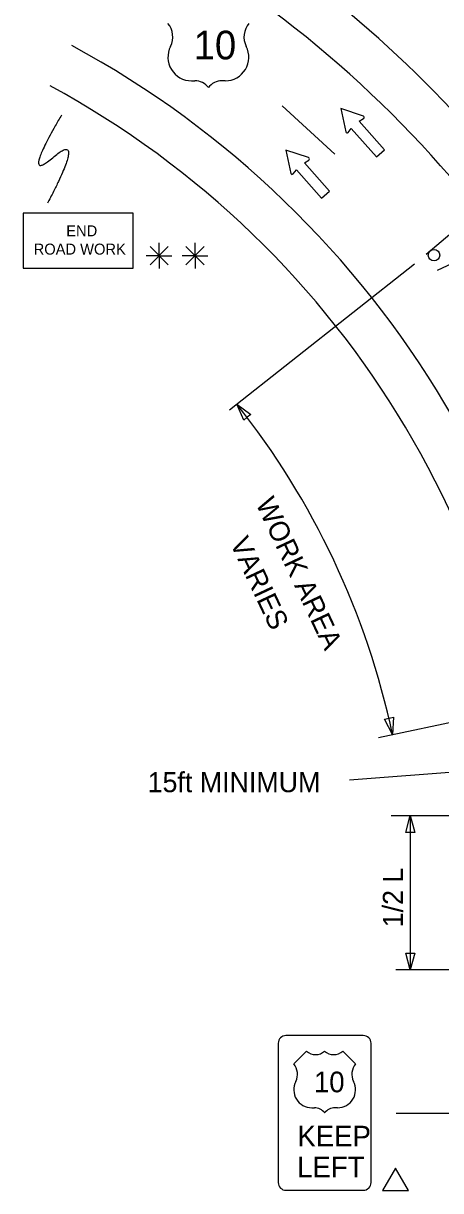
# Model space of a CAD drawing. Extents: x 16563 to 19504, y 6261 to 8279.
# Drawn here: x 16730.9 to 16876.6, y 7653.2 to 8060.6 of the extents above; entities that cross this region are included whole.
import ezdxf

# ---------------------------------------------------------------- set-up
doc = ezdxf.new("R2010")
doc.units = 0
for name, color, linetype in [('ALI_LEGAL_EX', 7, 'Continuous'), ('MT_SCRATCH_LEVEL_A', 7, 'Continuous'), ('MT_SCRATCH_LEVEL_E', 7, 'Continuous'), ('PAVT_EDGE_EX', 7, 'Continuous'), ('TRAFFIC_SIGNS_PR', 7, 'Continuous'), ('TYPICAL_EX', 7, 'Continuous'), ('TYPICAL_TEXT_DIMEN_PR', 7, 'Continuous')]:
    doc.layers.add(name, color=color, linetype=linetype)

msp = doc.modelspace()

# ---------------------------------------------------------------- linework, layer by layer
at = {"layer": 'ALI_LEGAL_EX'}
msp.add_lwpolyline([(16839.69, 8014.86), (16821.25, 8031.75)], dxfattribs=at)
msp.add_arc((16585.01, 7943.78), 364, 0, 40.1909, dxfattribs=at)
at = {"layer": 'MT_SCRATCH_LEVEL_A'}
for p, q in [((16889.81, 7995.4), (16871.52, 7979.86)), ((16875.47, 7974.42), (16897.61, 7984.74))]:
    msp.add_line(p, q, dxfattribs=at)
at = {"layer": 'MT_SCRATCH_LEVEL_E'}
for p, q in [((16841.74, 8030.81), (16843.46, 8022.67)), ((16849.64, 8028.15), (16841.74, 8030.81)), ((16841.74, 8030.81), (16843.46, 8022.67)), ((16849.64, 8028.15), (16841.74, 8030.81)), ((16848.2, 8026.37), (16849.74, 8027.31)), ((16848.2, 8026.37), (16849.74, 8027.31)), ((16856.99, 8016.45), (16848.2, 8026.37)), ((16856.99, 8016.45), (16848.2, 8026.37)), ((16844.28, 8022.47), (16845.4, 8023.89)), ((16844.28, 8022.47), (16845.4, 8023.89)), ((16845.4, 8023.89), (16854.19, 8013.97)), ((16845.4, 8023.89), (16854.19, 8013.97)), ((16822.58, 8016.35), (16824.31, 8008.2)), ((16830.49, 8013.68), (16822.58, 8016.35)), ((16822.58, 8016.35), (16824.31, 8008.2)), ((16830.49, 8013.68), (16822.58, 8016.35)), ((16854.19, 8013.97), (16856.99, 8016.45)), ((16854.19, 8013.97), (16856.99, 8016.45)), ((16825.12, 8008.01), (16826.25, 8009.43)), ((16825.12, 8008.01), (16826.25, 8009.43)), ((16826.25, 8009.43), (16835.04, 7999.51)), ((16826.25, 8009.43), (16835.04, 7999.51)), ((16829.05, 8011.91), (16830.58, 8012.85)), ((16829.05, 8011.91), (16830.58, 8012.85)), ((16837.84, 8001.99), (16829.05, 8011.91)), ((16837.84, 8001.99), (16829.05, 8011.91)), ((16835.04, 7999.51), (16837.84, 8001.99)), ((16835.04, 7999.51), (16837.84, 8001.99))]:
    msp.add_line(p, q, dxfattribs=at)
for centre, start, end in [((16849.48, 8027.7), 301.5941, 71.331), ((16849.48, 8027.7), 301.5941, 71.331), ((16843.92, 8022.77), 191.9827, 321.5217), ((16843.92, 8022.77), 191.9827, 321.5217), ((16830.33, 8013.24), 301.5941, 71.331), ((16830.33, 8013.24), 301.5941, 71.331), ((16824.76, 8008.3), 191.9827, 321.5217), ((16824.76, 8008.3), 191.9827, 321.5217)]:
    msp.add_arc(centre, 0.463, start, end, dxfattribs=at)
at = {"layer": 'PAVT_EDGE_EX'}
for radius, start in [(404, 21.0961), (388, 14.0482), (340, 0), (324, 0)]:
    msp.add_arc((16586.02, 7753.78), radius, start, 61.5719, dxfattribs=at)
at = {"layer": 'TRAFFIC_SIGNS_PR'}
for p, q in [((16819.92, 7704.61), (16819.92, 7656.01)), ((16849.62, 7707.31), (16822.62, 7707.31)), ((16852.32, 7656.01), (16852.32, 7704.61)), ((16822.62, 7653.31), (16849.62, 7653.31))]:
    msp.add_line(p, q, dxfattribs=at)
msp.add_lwpolyline([(16730.9, 7975.1), (16769.31, 7975.1), (16769.31, 7994.3), (16730.9, 7994.3)], close=True, dxfattribs=at)
msp.add_circle((16874.31, 7979.63), 2, dxfattribs=at)
for centre, start, end in [((16822.62, 7704.61), 90, 180), ((16849.62, 7704.61), 0, 90), ((16822.62, 7656.01), 180, 270), ((16849.62, 7656.01), 270, 0)]:
    msp.add_arc(centre, 2.7, start, end, dxfattribs=at)
at = {"layer": 'TYPICAL_EX'}
for p, q in [((16789.62, 8040.49), (16790.8, 8040.49)), ((16801.42, 8040.49), (16800.24, 8040.49)), ((16825.32, 7697.41), (16829.82, 7701.91)), ((16846.92, 7697.41), (16842.42, 7701.91)), ((16831.62, 7682.1), (16832.52, 7682.1)), ((16840.63, 7682.1), (16839.73, 7682.1))]:
    msp.add_line(p, q, dxfattribs=at)
for centre, radius, start, end in [((16775.78, 8055.83), 7.31, 333.0977, 40.1936), ((16815.26, 8055.83), 7.31, 139.8064, 206.9023), ((16789.63, 8048.74), 8.24, 152.6698, 269.9013), ((16801.41, 8048.74), 8.24, 270.0987, 27.3302), ((16790.81, 8034.59), 5.91, 37.1038, 90.1385), ((16800.23, 8034.59), 5.91, 89.8615, 142.8962), ((16832.97, 7705.19), 4.55, 226.1404, 313.8596), ((16839.27, 7705.19), 4.55, 226.1404, 313.8596), ((16821.06, 7693.81), 5.58, 333.0977, 40.1936), ((16851.19, 7693.81), 5.58, 139.8064, 206.9023), ((16831.63, 7688.4), 6.29, 152.6698, 269.9013), ((16840.62, 7688.4), 6.29, 270.0987, 27.3302), ((16832.53, 7677.59), 4.51, 37.1038, 90.1385), ((16839.72, 7677.59), 4.51, 89.8615, 142.8962)]:
    msp.add_arc(centre, radius, start, end, dxfattribs=at)
at = {"layer": 'TYPICAL_TEXT_DIMEN_PR'}
for p, q in [((16775.14, 7982.66), (16781.52, 7976.28)), ((16781.52, 7982.66), (16775.14, 7976.28)), ((16778.33, 7979.47), (16778.33, 7983.93)), ((16787.7, 7982.66), (16794.08, 7976.28)), ((16794.08, 7982.66), (16787.7, 7976.28)), ((16790.89, 7979.47), (16790.89, 7983.93)), ((16778.33, 7979.47), (16773.8, 7979.47)), ((16778.33, 7979.47), (16781.52, 7979.47)), ((16778.33, 7979.47), (16782.81, 7979.47)), ((16778.33, 7979.47), (16778.33, 7974.97)), ((16790.89, 7979.47), (16786.35, 7979.47)), ((16790.89, 7979.47), (16794.08, 7979.47)), ((16790.89, 7979.47), (16795.37, 7979.47)), ((16790.89, 7979.47), (16790.89, 7974.97)), ((16802.86, 7925.63), (16867.44, 7976.64)), ((16807.87, 7922.12), (16805.46, 7927.69)), ((16805.46, 7927.69), (16810.33, 7924.07)), ((16810.33, 7924.07), (16809.1, 7923.09)), ((16809.1, 7923.09), (16807.87, 7922.12)), ((16854.94, 7811.3), (16939.03, 7829.29)), ((16857.06, 7817.75), (16858.6, 7818.08)), ((16859.82, 7812.35), (16857.06, 7817.75)), ((16858.6, 7818.08), (16860.13, 7818.41)), ((16860.13, 7818.41), (16859.82, 7812.35)), ((16930, 7803.04), (16844.8, 7796.48)), ((16859.35, 7784.07), (16919.92, 7784.07)), ((16864.45, 7778.21), (16866.02, 7784.07)), ((16866.02, 7784.07), (16866.02, 7730.23)), ((16866.02, 7784.07), (16867.59, 7778.21)), ((16866.02, 7778.21), (16864.45, 7778.21)), ((16867.59, 7778.21), (16866.02, 7778.21)), ((16866.02, 7730.23), (16864.45, 7736.09)), ((16864.45, 7736.09), (16866.02, 7736.09)), ((16866.02, 7736.09), (16867.59, 7736.09)), ((16867.59, 7736.09), (16866.02, 7730.23)), ((16964.91, 7730.23), (16861.02, 7730.23)), ((16861.12, 7680.23), (16954.02, 7680.23))]:
    msp.add_line(p, q, dxfattribs=at)
msp.add_lwpolyline([(16860.83, 7661.01), (16856.31, 7653.18), (16865.36, 7653.18)], close=True, dxfattribs=at)
msp.add_arc((16586.02, 7753.78), 280, 12.0744, 38.3971, dxfattribs=at)
msp.add_open_spline([(16744.22, 8028.52), (16729.76, 8003.9), (16752.97, 8023.75), (16739.32, 7997.74)], degree=2, dxfattribs=at)

# ---------------------------------------------------------------- texts
at = {"layer": 'TRAFFIC_SIGNS_PR'}
for s, height, p in [('END', 3.832, (16745.9, 7986.23)), ('ROAD WORK', 3.832, (16734.51, 7979.84)), ('10', 7.2, (16832.37, 7687.51)), ('KEEP', 7.2, (16826.6, 7668.61)), ('LEFT', 7.2, (16826.5, 7657.81))]:
    msp.add_text(s, height=height, dxfattribs=at).set_placement(p)
at = {"layer": 'TYPICAL_EX'}
msp.add_text('10', height=10, dxfattribs=at).set_placement((16790.36, 8047.98))
at = {"layer": 'TYPICAL_TEXT_DIMEN_PR'}
for s, rotation, p in [('WORK AREA', 295.1762, (16811.9, 7893.09)), ('VARIES', 295.1762, (16802.9, 7879.31)), ('1/2 L', 90, (16863.46, 7745.09))]:
    msp.add_text(s, height=7, rotation=rotation, dxfattribs=at).set_placement(p)
msp.add_text('15ft MINIMUM', height=7, dxfattribs=at).set_placement((16774.3, 7792.23))

doc.saveas('drawing.dxf')
